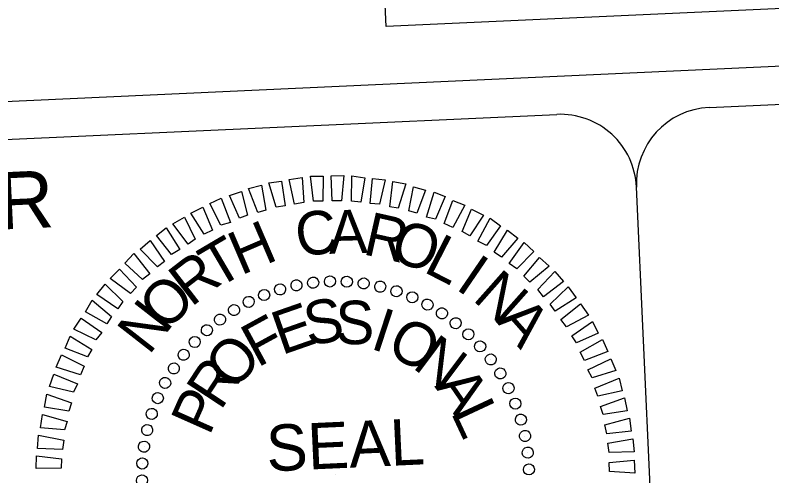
# Model space of a CAD drawing. Extents: x 1190067 to 1192950, y 891516 to 893460.
# Drawn here: x 1192835.37 to 1192875.08, y 892998.07 to 893022.25 of the extents above; entities that cross this region are included whole.
import ezdxf

# ---------------------------------------------------------------- set-up
doc = ezdxf.new("R2010")
doc.units = 0
for name, color, linetype in [('Sheet PE Seal Cell', 7, 'Continuous'), ('Sheet Sticker Exception Certification CELL', 7, 'Continuous'), ('Sheet Title CELL', 7, 'Continuous')]:
    doc.layers.add(name, color=color, linetype=linetype)

# ---------------------------------------------------------------- blocks, each defined once
blk = doc.blocks.new('STICKER EXCEPTION CERTIFICATION')
at = {"layer": 'Sheet Sticker Exception Certification CELL'}
for p, q in [((0, -0.47), (0, 0)), ((4.0008, -0.47), (0, -0.47))]:
    blk.add_line(p, q, dxfattribs=at)

msp = doc.modelspace()

# ---------------------------------------------------------------- linework, layer by layer
at = {"layer": 'Sheet PE Seal Cell'}
for p, q in [((1192851.005, 893008.226), (1192851.005, 893008.226)), ((1192851.894, 893008.287), (1192851.894, 893008.287)), ((1192852.787, 893008.267), (1192852.787, 893008.267)), ((1192853.663, 893008.165), (1192853.663, 893008.165)), ((1192849.258, 893007.862), (1192849.258, 893007.862)), ((1192850.14, 893008.065), (1192850.14, 893008.065)), ((1192854.521, 893008.022), (1192854.521, 893008.022)), ((1192855.384, 893007.778), (1192855.384, 893007.778)), ((1192848.419, 893007.581), (1192848.419, 893007.581)), ((1192856.209, 893007.451), (1192856.209, 893007.451)), ((1192847.625, 893007.22), (1192847.625, 893007.22)), ((1192857.017, 893007.082), (1192857.017, 893007.082)), ((1192846.855, 893006.779), (1192846.855, 893006.779)), ((1192857.768, 893006.61), (1192857.768, 893006.61)), ((1192846.107, 893006.279), (1192846.107, 893006.279)), ((1192858.501, 893006.096), (1192858.501, 893006.096)), ((1192845.422, 893005.741), (1192845.422, 893005.741)), ((1192859.156, 893005.518), (1192859.156, 893005.518)), ((1192844.782, 893005.104), (1192844.782, 893005.104)), ((1192859.793, 893004.878), (1192859.793, 893004.878)), ((1192844.204, 893004.449), (1192844.204, 893004.449)), ((1192860.332, 893004.193), (1192860.332, 893004.193)), ((1192843.691, 893003.716), (1192843.691, 893003.716)), ((1192860.832, 893003.446), (1192860.832, 893003.446)), ((1192843.218, 893002.964), (1192843.218, 893002.964)), ((1192861.273, 893002.675), (1192861.273, 893002.675)), ((1192842.85, 893002.157), (1192842.85, 893002.157)), ((1192861.633, 893001.881), (1192861.633, 893001.881)), ((1192842.523, 893001.331), (1192842.523, 893001.331)), ((1192861.915, 893001.043), (1192861.915, 893001.043)), ((1192842.278, 893000.468), (1192842.278, 893000.468)), ((1192862.118, 893000.16), (1192862.118, 893000.16)), ((1192842.135, 892999.611), (1192842.135, 892999.611)), ((1192862.279, 892999.296), (1192862.279, 892999.296)), ((1192842.033, 892998.734), (1192842.033, 892998.734)), ((1192862.34, 892998.406), (1192862.34, 892998.406)), ((1192852.176, 892998.124), (1192852.176, 892998.124))]:
    msp.add_line(p, q, dxfattribs=at)
for points in [[(1192850.026, 893012.337), (1192849.744, 893013.621), (1192850.428, 893013.734), (1192850.509, 893012.42)], [(1192851.033, 893012.484), (1192850.872, 893013.795), (1192851.54, 893013.805), (1192851.519, 893012.486)], [(1192852.005, 893012.509), (1192851.945, 893013.823), (1192852.613, 893013.834), (1192852.491, 893012.511)], [(1192853.019, 893012.494), (1192853.04, 893013.813), (1192853.713, 893013.722), (1192853.508, 893012.435)], [(1192848.1, 893011.904), (1192847.617, 893013.159), (1192848.298, 893013.332), (1192848.52, 893012.025)], [(1192849.061, 893012.171), (1192848.678, 893013.451), (1192849.343, 893013.542), (1192849.543, 893012.254)], [(1192853.997, 893012.377), (1192854.12, 893013.68), (1192854.792, 893013.609), (1192854.486, 893012.338)], [(1192855.039, 893012.201), (1192855.181, 893013.526), (1192855.877, 893013.395), (1192855.469, 893012.12)], [(1192847.141, 893011.597), (1192846.62, 893012.789), (1192847.239, 893013), (1192847.559, 893011.758)], [(1192856.022, 893011.983), (1192856.268, 893013.251), (1192856.905, 893013.077), (1192856.454, 893011.861)], [(1192856.949, 893011.66), (1192857.356, 893012.956), (1192857.934, 893012.739), (1192857.421, 893011.54)], [(1192846.165, 893011.228), (1192845.585, 893012.377), (1192846.181, 893012.648), (1192846.665, 893011.372)], [(1192857.877, 893011.318), (1192858.328, 893012.534), (1192858.968, 893012.28), (1192858.332, 893011.116)], [(1192845.294, 893010.762), (1192844.595, 893011.866), (1192845.209, 893012.177), (1192845.731, 893010.965)], [(1192858.829, 893010.895), (1192859.322, 893012.073), (1192859.945, 893011.757), (1192859.224, 893010.67)], [(1192844.446, 893010.237), (1192843.648, 893011.295), (1192844.26, 893011.647), (1192844.82, 893010.497)], [(1192859.643, 893010.385), (1192860.297, 893011.591), (1192860.843, 893011.19), (1192860.099, 893010.163)], [(1192843.579, 893009.691), (1192842.784, 893010.688), (1192843.292, 893011.096), (1192844.013, 893009.954)], [(1192860.5, 893009.816), (1192861.198, 893010.963), (1192861.744, 893010.542), (1192860.897, 893009.55)], [(1192842.838, 893009.049), (1192841.924, 893009.98), (1192842.451, 893010.43), (1192843.211, 893009.329)], [(1192861.297, 893009.224), (1192862.079, 893010.314), (1192862.586, 893009.851), (1192861.696, 893008.938)], [(1192842.058, 893008.384), (1192841.127, 893009.234), (1192841.59, 893009.741), (1192842.429, 893008.685)], [(1192862.058, 893008.549), (1192862.884, 893009.54), (1192863.392, 893009.077), (1192862.376, 893008.24)], [(1192841.423, 893007.646), (1192840.353, 893008.428), (1192840.838, 893008.916), (1192841.732, 893007.984)], [(1192862.799, 893007.854), (1192863.688, 893008.806), (1192864.138, 893008.28), (1192863.101, 893007.462)], [(1192840.75, 893006.845), (1192839.662, 893007.586), (1192840.083, 893008.132), (1192841.016, 893007.222)], [(1192863.442, 893007.092), (1192864.395, 893007.987), (1192864.806, 893007.418), (1192863.703, 893006.719)], [(1192840.178, 893006.048), (1192839.054, 893006.686), (1192839.412, 893007.29), (1192840.424, 893006.445)], [(1192864.006, 893006.287), (1192865.043, 893007.105), (1192865.455, 893006.516), (1192864.308, 893005.895)], [(1192839.608, 893005.211), (1192838.448, 893005.766), (1192838.826, 893006.351), (1192839.915, 893005.59)], [(1192864.573, 893005.421), (1192865.673, 893006.181), (1192865.965, 893005.566), (1192864.833, 893005.048)], [(1192839.163, 893004.319), (1192837.987, 893004.772), (1192838.261, 893005.413), (1192839.388, 893004.715)], [(1192865.017, 893004.57), (1192866.183, 893005.231), (1192866.476, 893004.596), (1192865.24, 893004.134)], [(1192838.801, 893003.37), (1192837.525, 893003.778), (1192837.8, 893004.419), (1192838.983, 893003.825)], [(1192865.425, 893003.636), (1192866.635, 893004.218), (1192866.886, 893003.601), (1192865.647, 893003.22)], [(1192838.437, 893002.462), (1192837.166, 893002.768), (1192837.4, 893003.408), (1192838.64, 893002.897)], [(1192865.793, 893002.679), (1192867.066, 893003.204), (1192867.218, 893002.542), (1192865.954, 893002.261)], [(1192838.178, 893001.477), (1192836.912, 893001.682), (1192837.023, 893002.357), (1192838.32, 893001.909)], [(1192866.08, 893001.72), (1192867.337, 893002.162), (1192867.49, 893001.48), (1192866.221, 893001.3)], [(1192837.959, 893000.494), (1192836.698, 893000.598), (1192836.808, 893001.293), (1192838.102, 893000.926)], [(1192866.307, 893000.757), (1192867.609, 893001.1), (1192867.701, 893000.415), (1192866.41, 893000.275)], [(1192837.845, 892999.455), (1192836.544, 892999.517), (1192836.594, 893000.208), (1192837.924, 892999.945)], [(1192866.472, 892999.792), (1192867.78, 893000.013), (1192867.852, 892999.328), (1192866.535, 892999.308)], [(1192837.788, 892998.479), (1192836.471, 892998.459), (1192836.481, 892999.129), (1192837.806, 892998.967)], [(1192866.539, 892998.781), (1192867.851, 892998.902), (1192867.882, 892998.214), (1192866.561, 892998.296)]]:
    msp.add_lwpolyline(points, close=True, dxfattribs=at)
for centre, major_axis in [((1192851.889, 893008.277), (-0.008, 0.291)), ((1192852.775, 893008.264), (0.017, 0.291)), ((1192849.271, 893007.857), (-0.083, 0.279)), ((1192850.131, 893008.073), (-0.059, 0.286)), ((1192851.006, 893008.214), (-0.034, 0.29)), ((1192853.657, 893008.173), (0.042, 0.288)), ((1192854.527, 893008.006), (0.067, 0.284)), ((1192848.434, 893007.567), (-0.107, 0.271)), ((1192855.379, 893007.763), (0.092, 0.277)), ((1192856.207, 893007.447), (0.116, 0.268)), ((1192847.625, 893007.205), (-0.131, 0.261)), ((1192857.005, 893007.06), (0.139, 0.257)), ((1192846.851, 893006.773), (-0.153, 0.248)), ((1192846.118, 893006.276), (-0.174, 0.234)), ((1192857.765, 893006.606), (0.16, 0.243)), ((1192858.483, 893006.086), (0.181, 0.229)), ((1192845.43, 893005.717), (-0.194, 0.218)), ((1192859.153, 893005.506), (0.2, 0.212)), ((1192844.794, 893005.1), (-0.212, 0.2)), ((1192859.77, 893004.87), (0.218, 0.194)), ((1192844.214, 893004.43), (-0.229, 0.181)), ((1192860.329, 893004.183), (0.234, 0.174)), ((1192843.695, 893003.712), (-0.243, 0.16)), ((1192860.826, 893003.449), (0.248, 0.153)), ((1192843.24, 893002.952), (-0.257, 0.139)), ((1192861.257, 893002.675), (0.261, 0.131)), ((1192842.853, 893002.155), (-0.268, 0.116)), ((1192861.619, 893001.866), (0.271, 0.107)), ((1192842.537, 893001.327), (-0.277, 0.092)), ((1192861.91, 893001.029), (0.279, 0.083)), ((1192842.295, 893000.475), (-0.284, 0.067)), ((1192862.126, 893000.17), (0.286, 0.059)), ((1192842.128, 892999.604), (-0.288, 0.042)), ((1192862.266, 892999.295), (0.29, 0.034)), ((1192842.037, 892998.723), (-0.291, 0.017)), ((1192862.33, 892998.411), (0.291, 0.008)), ((1192842.023, 892997.837), (-0.291, -0.008))]:
    msp.add_ellipse(centre, major_axis=major_axis, ratio=0.999708, dxfattribs=at)
at = {"layer": 'Sheet Title CELL'}
for p, q in [((1192366.316, 892996.287), (1192933.723, 893022.246)), ((1192871.787, 893017.41), (1192933.814, 893020.248)), ((1192783.971, 893013.393), (1192863.795, 893017.045)), ((1192870.899, 892949.299), (1192867.974, 893013.232))]:
    msp.add_line(p, q, dxfattribs=at)
for centre, start, end in [((1192871.97, 893013.414), 92.6195, 182.6195), ((1192863.978, 893013.049), 2.6195, 92.6195)]:
    msp.add_arc(centre, 4, start, end, dxfattribs=at)

# ---------------------------------------------------------------- block references
at = {"layer": 'Sheet Sticker Exception Certification CELL', "xscale": 20.000000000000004, "yscale": 20, "rotation": 2.619466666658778}
msp.add_blockref('STICKER EXCEPTION CERTIFICATION', (1192854.413, 893031.05), dxfattribs=at)

# ---------------------------------------------------------------- texts
at = {"layer": 'Sheet PE Seal Cell'}
for s, height, rotation, p in [('C', 2.283, 8.8393, (1192850.256, 893009.53)), ('A', 2.283, 1.6398, (1192851.848, 893009.724)), ('R', 2.283, 347.2406, (1192853.551, 893009.721)), ('H', 2.283, 23.2389, (1192847.218, 893008.58)), ('O', 2.283, 340.0406, (1192854.921, 893009.48)), ('T', 2.283, 30.4392, (1192845.934, 893007.852)), ('L', 2.283, 332.8403, (1192856.735, 893008.813)), ('R', 2.284, 37.64, (1192844.599, 893006.899)), ('I', 2.283, 325.6396, (1192858.418, 893007.917)), ('N', 2.284, 318.4384, (1192859.316, 893007.329)), ('O', 2.284, 44.8412, (1192843.261, 893005.581)), ('S', 2.283, 9.8751, (1192850.732, 893004.889)), ('N', 2.284, 52.043, (1192842.384, 893004.365)), ('E', 2.283, 19.2305, (1192849.355, 893004.401)), ('S', 2.283, 0.5199, (1192852.187, 893004.976)), ('A', 2.284, 311.2366, (1192860.565, 893006.19)), ('F', 2.283, 28.5865, (1192848.089, 893003.734)), ('I', 2.283, 341.8091, (1192853.94, 893004.772)), ('O', 2.283, 332.4529, (1192854.762, 893004.526)), ('N', 2.284, 323.0961, (1192856.154, 893003.779)), ('O', 2.284, 47.3007, (1192846.808, 893002.48)), ('R', 2.284, 56.6591, (1192846.145, 893001.456)), ('A', 2.284, 304.3797, (1192857.356, 893002.78)), ('P', 2.284, 66.0184, (1192845.557, 893000.132)), ('L', 2.284, 295.0203, (1192858.208, 893001.42)), ('SEAL', 2.4293, 2.6195, (1192848.601, 892998.304))]:
    msp.add_text(s, height=height, rotation=rotation, dxfattribs=at).set_placement(p)
at = {"layer": 'Sheet Title CELL'}
msp.add_text(' HYDRAULICS ENGINEER', height=3, rotation=2.6195, dxfattribs=at).set_placement((1192788.461, 893008.888))

doc.saveas('drawing.dxf')
